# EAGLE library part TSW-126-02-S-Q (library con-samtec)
THROUGH-HOLE .025" SQ POST HEADER Source: Samtec TSW.pdf
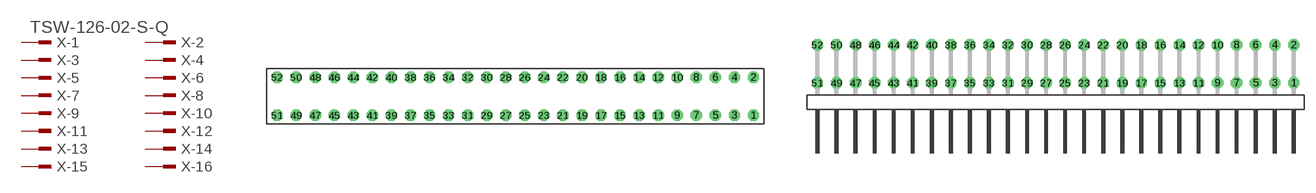
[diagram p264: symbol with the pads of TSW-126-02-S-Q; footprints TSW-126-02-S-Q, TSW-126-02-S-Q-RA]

Designator prefix X; gates -1=MPINV -2=MPIN -3=MPIN -4=MPIN -5=MPIN -6=MPIN -7=MPIN -8=MPIN -9=MPIN -10=MPIN -11=MPIN -12=MPIN -13=MPIN -14=MPIN -15=MPIN -16=MPIN -17=MPIN -18=MPIN -19=MPIN -20=MPIN -21=MPIN -22=MPIN -23=MPIN -24=MPIN -25=MPIN -26=MPIN -27=MPIN -28=MPIN -29=MPIN -30=MPIN -31=MPIN -32=MPIN -33=MPIN -34=MPIN -35=MPIN -36=MPIN -37=MPIN -38=MPIN -39=MPIN -40=MPIN -41=MPIN -42=MPIN -43=MPIN -44=MPIN -45=MPIN -46=MPIN -47=MPIN -48=MPIN -49=MPIN -50=MPIN -51=MPIN -52=MPIN

## TSW-126-02-S-Q (OC_FARNELL: unknown; OC_NEWARK: unknown)  [TSW-126-02-S-Q]
1  -1:1  pas
2  -2:1  pas
3  -3:1  pas
4  -4:1  pas
5  -5:1  pas
6  -6:1  pas
7  -7:1  pas
8  -8:1  pas
9  -9:1  pas
10  -10:1  pas
11  -11:1  pas
12  -12:1  pas
13  -13:1  pas
14  -14:1  pas
15  -15:1  pas
16  -16:1  pas
17  -17:1  pas
18  -18:1  pas
19  -19:1  pas
20  -20:1  pas
21  -21:1  pas
22  -22:1  pas
23  -23:1  pas
24  -24:1  pas
25  -25:1  pas
26  -26:1  pas
27  -27:1  pas
28  -28:1  pas
29  -29:1  pas
30  -30:1  pas
31  -31:1  pas
32  -32:1  pas
33  -33:1  pas
34  -34:1  pas
35  -35:1  pas
36  -36:1  pas
37  -37:1  pas
38  -38:1  pas
39  -39:1  pas
40  -40:1  pas
41  -41:1  pas
42  -42:1  pas
43  -43:1  pas
44  -44:1  pas
45  -45:1  pas
46  -46:1  pas
47  -47:1  pas
48  -48:1  pas
49  -49:1  pas
50  -50:1  pas
51  -51:1  pas
52  -52:1  pas

## TSW-126-02-S-Q-RA (OC_FARNELL: unknown; OC_NEWARK: unknown)  [TSW-126-02-S-Q-RA]
Pads as for TSW-126-02-S-Q

## Footprint TSW-126-02-S-Q (pad centres in mm)
THROUGH-HOLE .025" SQ POST HEADER Source: Samtec TSW.pdf
drill 1 pad 1.5 octagon: 1 31.75,-2.54; 2 31.75,2.54; 3 29.21,-2.54; 4 29.21,2.54; 5 26.67,-2.54; 6 26.67,2.54; 7 24.13,-2.54; 8 24.13,2.54; 9 21.59,-2.54; 10 21.59,2.54; 11 19.05,-2.54; 12 19.05,2.54; 13 16.51,-2.54; 14 16.51,2.54; 15 13.97,-2.54; 16 13.97,2.54; 17 11.43,-2.54; 18 11.43,2.54; 19 8.89,-2.54; 20 8.89,2.54; 21 6.35,-2.54; 22 6.35,2.54; 23 3.81,-2.54; 24 3.81,2.54; 25 1.27,-2.54; 26 1.27,2.54; 27 -1.27,-2.54; 28 -1.27,2.54; 29 -3.81,-2.54; 30 -3.81,2.54; 31 -6.35,-2.54; 32 -6.35,2.54; 33 -8.89,-2.54; 34 -8.89,2.54; 35 -11.43,-2.54; 36 -11.43,2.54; 37 -13.97,-2.54; 38 -13.97,2.54; 39 -16.51,-2.54; 40 -16.51,2.54; 41 -19.05,-2.54; 42 -19.05,2.54; 43 -21.59,-2.54; 44 -21.59,2.54; 45 -24.13,-2.54; 46 -24.13,2.54; 47 -26.67,-2.54; 48 -26.67,2.54; 49 -29.21,-2.54; 50 -29.21,2.54; 51 -31.75,-2.54; 52 -31.75,2.54

## Footprint TSW-126-02-S-Q-RA (pad centres in mm)
THROUGH-HOLE .025" SQ POST HEADER Source: Samtec TSW.pdf
drill 1 pad 1.5 octagon: 1 31.75,1.524; 2 31.75,6.604; 3 29.21,1.524; 4 29.21,6.604; 5 26.67,1.524; 6 26.67,6.604; 7 24.13,1.524; 8 24.13,6.604; 9 21.59,1.524; 10 21.59,6.604; 11 19.05,1.524; 12 19.05,6.604; 13 16.51,1.524; 14 16.51,6.604; 15 13.97,1.524; 16 13.97,6.604; 17 11.43,1.524; 18 11.43,6.604; 19 8.89,1.524; 20 8.89,6.604; 21 6.35,1.524; 22 6.35,6.604; 23 3.81,1.524; 24 3.81,6.604; 25 1.27,1.524; 26 1.27,6.604; 27 -1.27,1.524; 28 -1.27,6.604; 29 -3.81,1.524; 30 -3.81,6.604; 31 -6.35,1.524; 32 -6.35,6.604; 33 -8.89,1.524; 34 -8.89,6.604; 35 -11.43,1.524; 36 -11.43,6.604; 37 -13.97,1.524; 38 -13.97,6.604; 39 -16.51,1.524; 40 -16.51,6.604; 41 -19.05,1.524; 42 -19.05,6.604; 43 -21.59,1.524; 44 -21.59,6.604; 45 -24.13,1.524; 46 -24.13,6.604; 47 -26.67,1.524; 48 -26.67,6.604; 49 -29.21,1.524; 50 -29.21,6.604; 51 -31.75,1.524; 52 -31.75,6.604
